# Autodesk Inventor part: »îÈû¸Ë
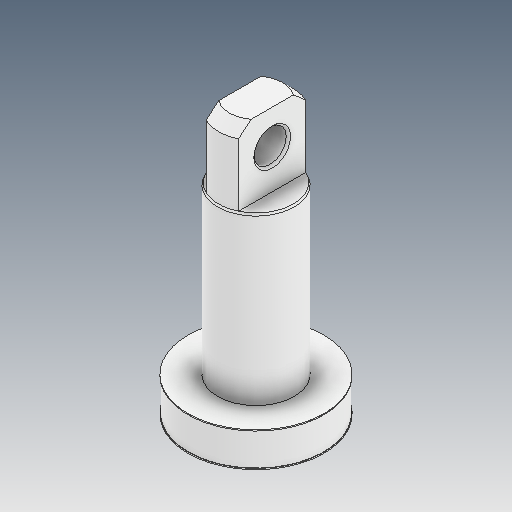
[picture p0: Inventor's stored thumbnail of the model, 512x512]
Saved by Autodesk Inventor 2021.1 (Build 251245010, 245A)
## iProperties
Created: 2021-05
Part Number: »îÈû¸Ë
Material: Ogólny
Document SubType Name: Modeling
Designer: user
Density: 1 g/cm^3
Appearance: Domyślna
Author: user
Revision Number: ÈÎºÎ
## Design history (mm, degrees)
feature "µ¹½Ç2"
node "Bryła1"
